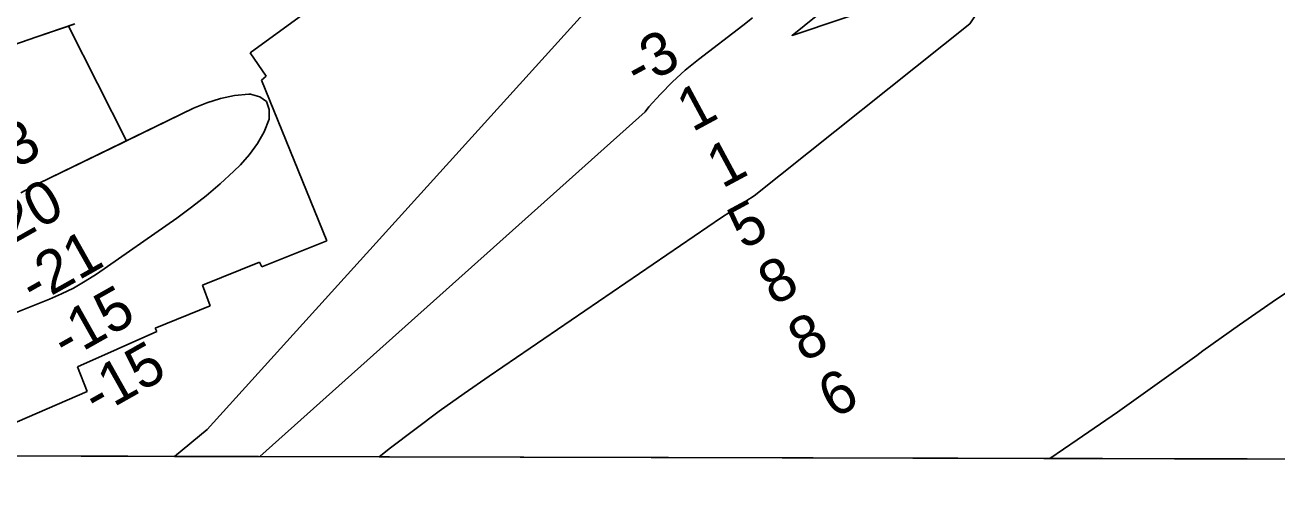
# Model space of a CAD drawing. Extents: x 3177385 to 3215275, y 903885 to 929304.
# Drawn here: x 3182745 to 3184706, y 909264 to 910009 of the extents above; entities that cross this region are included whole.
import ezdxf

# ---------------------------------------------------------------- set-up
doc = ezdxf.new("R2010")
doc.units = 0
for name, color, linetype in [('V-GRID-FRAM', 7, 'Continuous'), ('V-RIVR-RANG', 7, 'Continuous'), ('V-RRAP-RVMT', 7, 'Continuous'), ('V-STRM-FLOW', 7, 'Continuous'), ('V-TOPO-DPTH', 7, 'Continuous'), ('V-TOPO-MINR', 7, 'Continuous')]:
    doc.layers.add(name, color=color, linetype=linetype)

msp = doc.modelspace()

# ---------------------------------------------------------------- linework, layer by layer
at = {"layer": 'V-GRID-FRAM'}
msp.add_lwpolyline([(3181653.7, 927525.9), (3181603.5, 909337.1), (3212939.2, 909264.2), (3212973.6, 927453), (3181653.7, 927525.9)], dxfattribs=at)
at = {"layer": 'V-RRAP-RVMT'}
for p, q in [((3183185.4, 910029.8), (3183097.2, 909965.7)), ((3183097.2, 909965.7), (3183122.4, 909929.1)), ((3183122.4, 909929.1), (3183115.2, 909922.9)), ((3183115.2, 909922.9), (3183217.6, 909671.1)), ((3183217.6, 909671.1), (3183115.3, 909630.4)), ((3183112.1, 909637.9), (3183022.7, 909602)), ((3183115.3, 909630.4), (3183112.1, 909637.9)), ((3183022.7, 909602), (3183034.7, 909569.8)), ((3183034.7, 909569.8), (3182948.6, 909534.4)), ((3182950.8, 909529.4), (3182827, 909474.2)), ((3182948.6, 909534.4), (3182950.8, 909529.4)), ((3182827, 909474.2), (3182841.7, 909435.6)), ((3182841.7, 909435.6), (3182716.4, 909381.3))]:
    msp.add_line(p, q, dxfattribs=at)
at = {"layer": 'V-STRM-FLOW'}
msp.add_lwpolyline([(3184106.6, 910046.6), (3183946.1, 909992.9), (3184077.8, 910099.2)], dxfattribs=at)
at = {"layer": 'V-TOPO-DPTH'}
for points in [[(3183299.6, 909333.1), (3183317.1, 909347.1), (3183355.2, 909376.1), (3183393.5, 909404.6), (3183432.4, 909432.4), (3183471.7, 909459.7), (3183835.7, 909707.7), (3183848.4, 909716.3), (3183861.1, 909724.8), (3183873.9, 909733.3), (3183886.8, 909741.7), (3184224.8, 910011.3), (3184234.2, 910025.3), (3184244.3, 910039.2), (3184260.2, 910058.9), (3184277.4, 910077.1), (3184296.6, 910093.3), (3184317.1, 910108.1), (3184565.2, 910266.1), (3184595.2, 910285.2), (3184625.4, 910304.1), (3184655.6, 910323), (3184685.8, 910341.7), (3184751.4, 910382.2)], [(3182762.3, 910073.5), (3182738.4, 910060.3), (3182705.1, 910041.4), (3182672, 910022.2), (3182607.7, 909984.6), (3182606.8, 909984.1), (3182605.1, 909982.8), (3182604.4, 909982.1), (3182581, 909959.8), (3182578.3, 909952.5), (3182578.5, 909946.5), (3182583, 909942.6), (3182590.3, 909939.9), (3182591.9, 909940.1), (3182609.7, 909942.7), (3182627.3, 909946.1), (3182644.7, 909950.6), (3182661.9, 909955.9), (3182763, 909990.5), (3182803.5, 910004.4), (3182812.5, 910007.5), (3182903.6, 909828), (3182898.5, 909825.5)], [(3183659.2, 910071.3), (3183029.9, 909375.8), (3182978.9, 909333.9), (3183299.6, 909333.1)], [(3183659.2, 910071.3), (3183029.9, 909375.8), (3182978.9, 909333.9)], [(3182661.9, 909955.9), (3182763, 909990.5), (3182822.7, 910011)], [(3182812.5, 910007.5), (3182822.7, 910011)], [(3183050.7, 909894.3), (3183029.3, 909887.5), (3183008.3, 909878.8), (3182903.6, 909828), (3182812.5, 910007.5)], [(3184224.8, 910011.3), (3183886.8, 909741.7), (3183873.9, 909733.3), (3183861.1, 909724.8), (3183848.4, 909716.3), (3183835.7, 909707.7), (3183471.7, 909459.7), (3183432.4, 909432.4), (3183393.5, 909404.6), (3183355.2, 909376.1), (3183317.1, 909347.1), (3183299.6, 909333.1), (3186019.2, 909326.8)], [(3182612.5, 909512.1), (3182782.7, 909579.8), (3182801.9, 909588.2), (3182820.6, 909597.5), (3182838.7, 909608), (3182856.4, 909619.4), (3182982.2, 909707), (3183005.6, 909724.1), (3183028.4, 909741.9), (3183050.3, 909760.8), (3183071.6, 909780.4), (3183082.1, 909790.5), (3183096.4, 909806.5), (3183108.9, 909823.5), (3183119, 909842.2), (3183127.2, 909861.9), (3183127.1, 909877.2), (3183122.8, 909889.3), (3183112.3, 909896.8), (3183097.6, 909901.1), (3183095.3, 909901), (3183072.8, 909898.6), (3183050.7, 909894.3)], [(3182612.5, 909512.1), (3182782.7, 909579.8), (3182801.9, 909588.2), (3182820.6, 909597.5), (3182838.7, 909608), (3182856.4, 909619.4), (3182982.2, 909707), (3183005.6, 909724.1), (3183028.4, 909741.9), (3183050.3, 909760.8), (3183071.6, 909780.4), (3183082.1, 909790.5), (3183096.4, 909806.5), (3183108.9, 909823.5), (3183119, 909842.2), (3183127.2, 909861.9), (3183127.1, 909877.2), (3183122.8, 909889.3), (3183112.3, 909896.8), (3183097.6, 909901.1), (3183095.3, 909901), (3183072.8, 909898.6), (3183050.7, 909894.3)], [(3183050.7, 909894.3), (3183029.3, 909887.5), (3183008.3, 909878.8), (3182765.8, 909761), (3182751.7, 909753.8), (3182737.9, 909746.3)], [(3182898.5, 909825.5), (3182765.8, 909761), (3182751.7, 909753.8), (3182737.9, 909746.3)], [(3182978.9, 909333.9), (3182685.7, 909334.6), (3182696.9, 909344.9), (3182699.7, 909353), (3182699.3, 909359.4), (3182694.2, 909363.3), (3182686, 909365.6), (3182606.6, 909348.3), (3182555.5, 909334.9), (3181885.9, 909336.4)]]:
    msp.add_lwpolyline(points, dxfattribs=at)
at = {"layer": 'V-TOPO-MINR'}
for points in [[(3183299.6, 909333.1), (3183317.1, 909347.1), (3183355.2, 909376.1), (3183393.5, 909404.6), (3183432.4, 909432.4), (3183471.7, 909459.7), (3183835.7, 909707.7), (3183848.4, 909716.3), (3183861.1, 909724.8), (3183873.9, 909733.3), (3183886.8, 909741.7), (3184224.8, 910011.3), (3184234.2, 910025.3), (3184244.3, 910039.2), (3184260.2, 910058.9), (3184277.4, 910077.1), (3184296.6, 910093.3), (3184317.1, 910108.1), (3184565.2, 910266.1), (3184595.2, 910285.2), (3184625.4, 910304.1), (3184655.6, 910323), (3184685.8, 910341.7), (3184751.4, 910382.2)], [(3182978.9, 909333.9), (3183029.9, 909375.8), (3183659.2, 910071.3)], [(3183112.5, 909333.6), (3183715.8, 909873.3), (3183722, 909880.9), (3183739.9, 909901), (3183758.7, 909920.3), (3183778.8, 909938.3), (3183799.6, 909955.4), (3183868.8, 910008.2), (3183884.1, 910020.3)], [(3182661.9, 909955.9), (3182763, 909990.5), (3182822.7, 910011)], [(3182661.9, 909955.9), (3182763, 909990.5), (3182822.7, 910011)], [(3182612.5, 909512.1), (3182782.7, 909579.8), (3182801.9, 909588.2), (3182820.6, 909597.5), (3182838.7, 909608), (3182856.4, 909619.4), (3182982.2, 909707), (3183005.6, 909724.1), (3183028.4, 909741.9), (3183050.3, 909760.8), (3183071.6, 909780.4), (3183082.1, 909790.5), (3183096.4, 909806.5), (3183108.9, 909823.5), (3183119, 909842.2), (3183127.2, 909861.9), (3183127.1, 909877.2), (3183122.8, 909889.3), (3183112.3, 909896.8), (3183097.6, 909901.1), (3183095.3, 909901), (3183072.8, 909898.6), (3183050.7, 909894.3)], [(3182612.5, 909512.1), (3182782.7, 909579.8), (3182801.9, 909588.2), (3182820.6, 909597.5), (3182838.7, 909608), (3182856.4, 909619.4), (3182982.2, 909707), (3183005.6, 909724.1), (3183028.4, 909741.9), (3183050.3, 909760.8), (3183071.6, 909780.4), (3183082.1, 909790.5), (3183096.4, 909806.5), (3183108.9, 909823.5), (3183119, 909842.2), (3183127.2, 909861.9), (3183127.1, 909877.2), (3183122.8, 909889.3), (3183112.3, 909896.8), (3183097.6, 909901.1), (3183095.3, 909901), (3183072.8, 909898.6), (3183050.7, 909894.3)], [(3183050.7, 909894.3), (3183029.3, 909887.5), (3183008.3, 909878.8), (3182765.8, 909761), (3182751.7, 909753.8), (3182737.9, 909746.3)], [(3183050.7, 909894.3), (3183029.3, 909887.5), (3183008.3, 909878.8), (3182765.8, 909761), (3182751.7, 909753.8), (3182737.9, 909746.3)], [(3184349.7, 909330.7), (3184393, 909360), (3184455.9, 909403.3), (3184518.3, 909447.4), (3184580.3, 909492), (3184589.8, 909498.9), (3184647.2, 909539.8), (3184705.2, 909580), (3184763.9, 909619)]]:
    msp.add_lwpolyline(points, dxfattribs=at)

# ---------------------------------------------------------------- texts
at = {"layer": 'V-RIVR-RANG'}
for s, rotation, p in [('-3', 28.3158, (3183704.9, 909908.7)), ('1', 28.3158, (3183789.9, 909840.9)), ('-13', 29.4133, (3182661.5, 909744.5)), ('1', 28.3158, (3183836.6, 909752.5)), ('-20', 29.4133, (3182697.5, 909650)), ('5', 28.3158, (3183869.7, 909656.7)), ('-21', 29.4133, (3182758.9, 909569.8)), ('8', 28.3158, (3183917.3, 909568.8)), ('-15', 29.4133, (3182808.7, 909483.1)), ('8', 28.3158, (3183964.1, 909480.4)), ('-15', 29.4133, (3182857.3, 909395.7)), ('6', 28.3158, (3184011.3, 909392.2))]:
    msp.add_text(s, height=67, rotation=rotation, dxfattribs=at).set_placement(p)

doc.saveas('drawing.dxf')
